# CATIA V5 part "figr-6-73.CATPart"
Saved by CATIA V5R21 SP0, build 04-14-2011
Part number: Part2
Bounding box of the stored display mesh (mm): x -37.886 to 37.886, y -61.415 to 61.415, z 0 to 29
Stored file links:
  D:\CATIA V5R21 E-RESOURCES\CATIA-V5R21\catia-v5r21-prt\c06-catia-v5r21-prt\c06-catia-v5r21-figr-6-73.CATPart
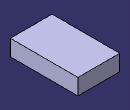
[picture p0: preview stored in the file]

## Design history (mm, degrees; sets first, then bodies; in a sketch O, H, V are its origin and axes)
Body1 (main body)
  Sketch1 on xy-plane, origin (0, 0, 0), H (1, 0, 0), V (0, 1, 0)
    line L1 (37.8862, 61.4155) -> (37.8862, -61.4155)
    line L2 (37.8862, -61.4155) -> (-37.8862, -61.4155)
    line L3 (-37.8862, -61.4155) -> (-37.8862, 61.4155)
    line L4 (-37.8862, 61.4155) -> (37.8862, 61.4155)
    vertical: L1 V, L3 V
    horizontal: L2 H, L4 H
    equidistance: L1 L3 O, L2 L4 O
  Pad1: profile Sketch1, direction (0, 0, 1), length 29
